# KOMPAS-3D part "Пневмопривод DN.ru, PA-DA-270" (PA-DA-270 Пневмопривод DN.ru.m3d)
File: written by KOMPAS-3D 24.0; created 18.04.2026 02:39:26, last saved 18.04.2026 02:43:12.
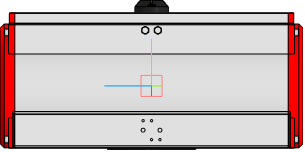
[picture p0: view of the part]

Document properties: Автор: DN.ru; Полное имя файла: C:\Работа\PA-DA-х Пневмопривод DN.ru\270\PA-DA-270 Пневмопривод DN.ru.m3d

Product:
- Part/product: Пневмопривод DN.ru  | designation PA-DA-270
    Масса: 97
    Раздел спецификации: Прочие изделия
    Примечание: D290-00301

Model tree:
1. Операция без истории:1

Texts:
  PA-DA-270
